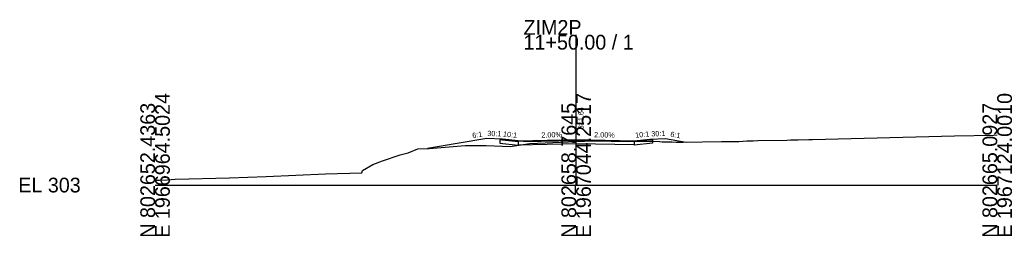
# Model space of a CAD drawing. Extents: x 1950845 to 1951408, y 736831 to 740365.
# Drawn here: x 1950844.5 to 1951033.1, y 738331.5 to 738372.6 of the extents above; entities that cross this region are included whole.
import ezdxf

# ---------------------------------------------------------------- set-up
doc = ezdxf.new("R2010")
doc.units = 0
for name, color, linetype in [('RD_GPK_XS_Cell', 7, 'Continuous'), ('RD_XS_Base', 7, 'Continuous'), ('RD_XS_EarthShd', 7, 'Continuous'), ('RD_XS_ExGround', 7, 'Continuous'), ('RD_XS_Pave', 7, 'Continuous'), ('RD_XS_PaveOvlay', 7, 'Continuous'), ('RD_XS_TieSlope', 7, 'Continuous'), ('RD_XS_TX_Elev_PR', 7, 'Continuous'), ('RD_XS_TX_Slope', 7, 'Continuous')]:
    doc.layers.add(name, color=color, linetype=linetype)

msp = doc.modelspace()

# ---------------------------------------------------------------- linework, layer by layer
at = {"layer": 'RD_GPK_XS_Cell'}
for p, q in [((1950950.22, 738341.19), (1950950.22, 738369.71)), ((1950870.22, 738341.19), (1950950.22, 738341.19)), ((1950950.22, 738341.19), (1951030.22, 738341.19))]:
    msp.add_line(p, q, dxfattribs=at)
at = {"layer": 'RD_XS_Base'}
for points in [[(1950939.22, 738349.45), (1950936.22, 738349.75), (1950935.72, 738349.8)], [(1950935.72, 738349.8), (1950935.72, 738349.14)], [(1950935.72, 738349.14), (1950939.22, 738348.79)], [(1950939.22, 738349.45), (1950939.22, 738348.79)], [(1950961.22, 738348.8), (1950950.22, 738349.01), (1950939.22, 738348.79)], [(1950940.22, 738349.47), (1950950.22, 738349.67), (1950960.22, 738349.47)], [(1950961.22, 738349.45), (1950964.22, 738349.75), (1950964.72, 738349.8)], [(1950961.22, 738349.45), (1950961.22, 738348.79)], [(1950964.72, 738349.14), (1950961.22, 738348.79)], [(1950964.72, 738349.8), (1950964.72, 738349.14)]]:
    msp.add_lwpolyline(points, dxfattribs=at)
at = {"layer": 'RD_XS_EarthShd'}
for points in [[(1950936.22, 738349.91), (1950933.22, 738350.01)], [(1950964.22, 738349.91), (1950967.22, 738350.01)]]:
    msp.add_lwpolyline(points, dxfattribs=at)
at = {"layer": 'RD_XS_ExGround'}
msp.add_lwpolyline([(1950870.22, 738342.11), (1950871.08, 738342.14), (1950872.49, 738342.19), (1950874.01, 738342.28), (1950884.33, 738342.59), (1950891.32, 738342.81), (1950902.58, 738343.32), (1950909.53, 738343.49), (1950909.63, 738343.94), (1950911.59, 738345.1), (1950913.43, 738345.81), (1950916.79, 738346.92), (1950918.29, 738347.29), (1950920.17, 738348.06), (1950922.32, 738348.15), (1950929.14, 738348.68), (1950933.15, 738348.71), (1950937.69, 738348.53), (1950941.42, 738349.1), (1950945.78, 738349.27), (1950950.22, 738349.44), (1950953.48, 738349.56), (1950958.67, 738349.55), (1950966.14, 738349.45), (1950966.56, 738349.38), (1950967.46, 738349.37), (1950968.39, 738349.37), (1950969.2, 738349.36), (1950970.54, 738349.35), (1950977.83, 738349.45), (1950978.13, 738349.46), (1950978.83, 738349.49), (1950979.71, 738349.48), (1950981.14, 738349.49), (1950982.63, 738349.57), (1950983.85, 738349.58), (1950984.75, 738349.62), (1950990.23, 738349.72), (1950990.96, 738349.76), (1950992.07, 738349.8), (1950992.4, 738349.8), (1950994.44, 738349.83), (1950995.14, 738349.87), (1951022.08, 738350.51), (1951029.51, 738350.68), (1951030.22, 738350.7)], dxfattribs=at)
at = {"layer": 'RD_XS_Pave'}
for points in [[(1950939.22, 738349.61), (1950936.22, 738349.91)], [(1950936.22, 738349.91), (1950936.22, 738349.75)], [(1950936.22, 738349.75), (1950939.22, 738349.45)], [(1950939.22, 738349.45), (1950939.22, 738349.61)], [(1950961.22, 738349.61), (1950964.22, 738349.91)], [(1950964.22, 738349.75), (1950961.22, 738349.45)], [(1950961.22, 738349.45), (1950961.22, 738349.61)], [(1950964.22, 738349.91), (1950964.22, 738349.75)]]:
    msp.add_lwpolyline(points, dxfattribs=at)
at = {"layer": 'RD_XS_PaveOvlay'}
for points in [[(1950939.22, 738349.61), (1950950.22, 738349.83), (1950961.22, 738349.61)], [(1950961.22, 738349.45), (1950950.22, 738349.67), (1950939.22, 738349.45)], [(1950939.22, 738349.61), (1950939.22, 738349.45)], [(1950961.22, 738349.61), (1950961.22, 738349.45)]]:
    msp.add_lwpolyline(points, dxfattribs=at)
at = {"layer": 'RD_XS_TieSlope'}
for points in [[(1950933.22, 738350.01), (1950921.95, 738348.13)], [(1950967.22, 738350.01), (1950971.13, 738349.36)]]:
    msp.add_lwpolyline(points, dxfattribs=at)

# ---------------------------------------------------------------- texts
at = {"layer": 'RD_GPK_XS_Cell'}
for s, p in [('ZIM2P', (1950940.22, 738369.71)), ('11+50.00 / 1', (1950940.22, 738366.91)), ('EL 303', (1950844.22, 738339.79))]:
    msp.add_text(s, height=2.8, dxfattribs=at).set_placement(p)
for s, p in [('E 1966964.5024', (1950873.02, 738331.19)), ('E 1967044.2517', (1950953.02, 738331.19)), ('E 1967124.0010', (1951033.02, 738331.19)), ('N 802652.4363', (1950870.22, 738331.19)), ('N 802658.7645', (1950950.22, 738331.19)), ('N 802665.0927', (1951030.22, 738331.19))]:
    msp.add_text(s, height=2.8, rotation=90, dxfattribs=at).set_placement(p)
at = {"layer": 'RD_XS_TX_Elev_PR'}
msp.add_text('311.64', height=1, rotation=90, dxfattribs=at).set_placement((1950951.62, 738351.78))
at = {"layer": 'RD_XS_TX_Slope'}
for s, rotation, p in [('6:1', 9.4642, (1950930.57, 738350.08)), ('30:1', 358.0908, (1950933.33, 738350.51)), ('10:1', 354.2894, (1950936.28, 738350.41)), ('2.00%', 1.1458, (1950943.61, 738350.2)), ('2.00%', 358.8542, (1950953.63, 738350.26)), ('10:1', 5.7106, (1950961.48, 738350.14)), ('30:1', 1.9092, (1950964.5, 738350.42)), ('6:1', 350.5358, (1950968.06, 738350.38))]:
    msp.add_text(s, height=1, rotation=rotation, dxfattribs=at).set_placement(p)

doc.saveas('drawing.dxf')
